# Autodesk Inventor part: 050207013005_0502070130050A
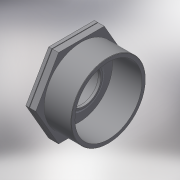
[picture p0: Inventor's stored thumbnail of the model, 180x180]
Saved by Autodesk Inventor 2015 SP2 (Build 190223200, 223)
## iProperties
Created: 2017-05
Part Number: 050207013005_0502070130050A
Material: Generic
Description: PLASSON REDUCING BUSHING 1.1/4"-1/2"
Document SubType Name: Modeling
Designer: KIM
Density: 1 g/cm^3
Appearance: Default
Author: KIM
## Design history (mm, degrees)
derived "050207.ipt"
feature "Solid1::050207.ipt"
tag "TaggingFeature1"
body "Solid1"
other parameters: "d1" = 41.91, "d2" = 46, "d5" = 21, "d8" = 0.37, "d12" = 0, "d15" = 37, "d19" = 0, "d30" = 9.25, "d31" = 4.625, "d33" = 18.631, "d34" = 37.719, "d36" = 2.3, "d37" = 22.3572, "d38" = 24.42, "d39" = 16.7679, "d40" = 2.1, "d41" = 0, "H_" = 37, "R_" = 41.91, "E_" = 46, "l_2" = 21, "Rp_" = 18.631
